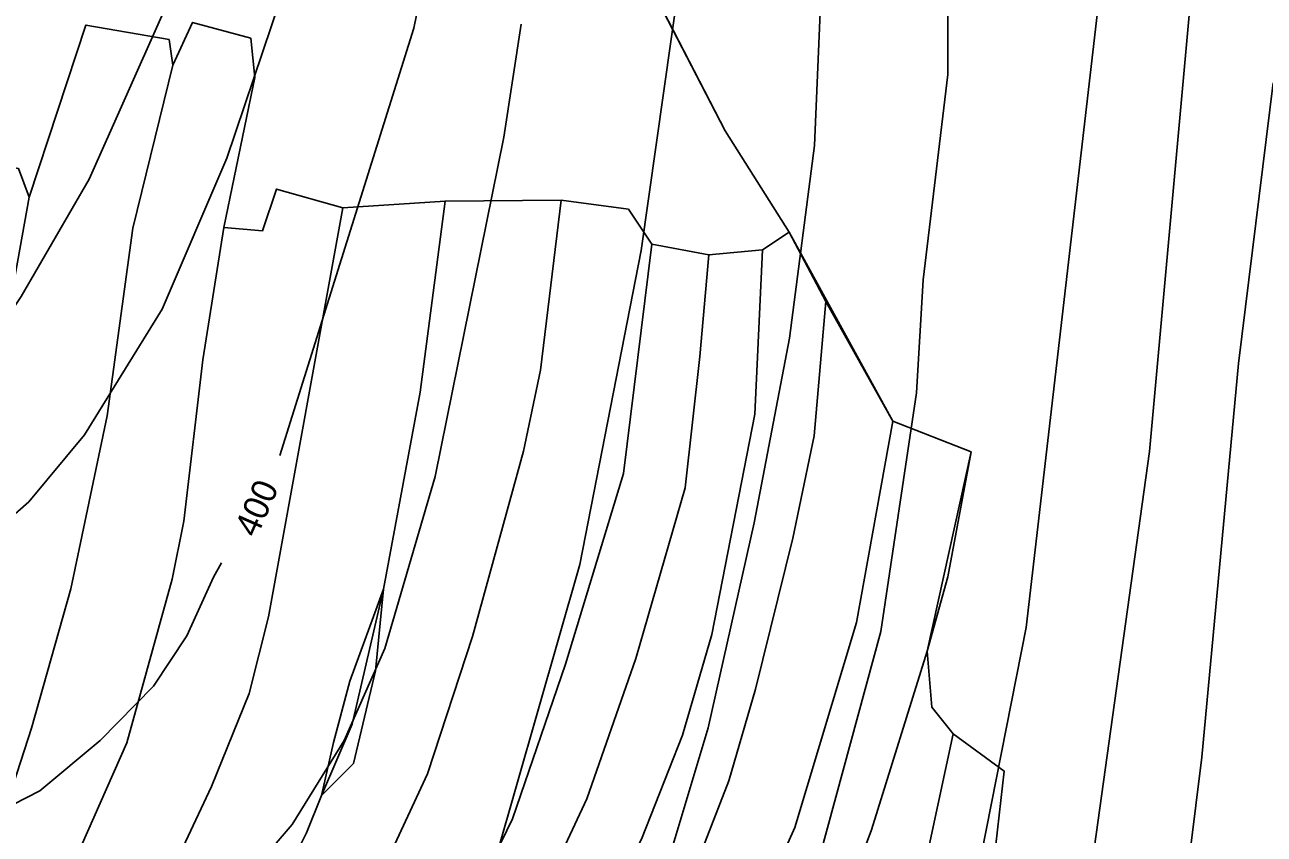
# Model space of a CAD drawing. Extents: x -510989 to -501240, y -1184665 to -1176098.
# Drawn here: x -501918.7 to -501623.1, y -1183267.4 to -1183074.2 of the extents above; entities that cross this region are included whole.
import ezdxf

# ---------------------------------------------------------------- set-up
doc = ezdxf.new("R2010")
doc.units = 0
for name, color, linetype in [('lesni_pozemek', 7, 'Continuous'), ('orna_puda', 7, 'Continuous'), ('popis', 7, 'Continuous'), ('STAV_zaplavove_uzemi', 7, 'Continuous'), ('trvaly_travni_porost', 7, 'Continuous'), ('vrstevnice_01', 7, 'Continuous'), ('vrstevnice_02', 7, 'Continuous'), ('vrstevnice_04', 7, 'Continuous')]:
    doc.layers.add(name, color=color, linetype=linetype)

msp = doc.modelspace()

# ---------------------------------------------------------------- linework, layer by layer
at = {"layer": 'lesni_pozemek'}
msp.add_lwpolyline([(-501783.55, -1183037.66), (-501751.63, -1183099.46), (-501736.36, -1183123.66), (-501742.71, -1183127.87), (-501755.51, -1183129.09), (-501769.14, -1183126.53), (-501774.69, -1183118.15), (-501790.7, -1183116.04), (-501818.4, -1183116.24), (-501842.79, -1183117.88), (-501858.62, -1183113.36), (-501861.95, -1183123.31), (-501871.15, -1183122.57), (-501863.8, -1183086.72), (-501864.77, -1183077.37), (-501878.63, -1183073.61), (-501883.32, -1183083.77), (-501884.24, -1183077.69), (-501904.1, -1183074.23), (-501917.6, -1183115.27), (-501920.15, -1183108.47)], dxfattribs=at)
at = {"layer": 'orna_puda'}
for points in [[(-501904.1, -1183074.23), (-501884.24, -1183077.69), (-501883.32, -1183083.77), (-501892.93, -1183122.67), (-501899.03, -1183167.53), (-501907.67, -1183208.78), (-501917.05, -1183242.02), (-501926.59, -1183271.34), (-501937.55, -1183292.58), (-501958.27, -1183326.06), (-501975.2, -1183320.45), (-501955.04, -1183286.9), (-501945.61, -1183264.95), (-501940.28, -1183250.99), (-501931.27, -1183221.12), (-501924.09, -1183185.46), (-501925.8, -1183185.09), (-501927.7, -1183184.68), (-501926.03, -1183161.85), (-501917.6, -1183115.27)], [(-501864.77, -1183077.37), (-501863.8, -1183086.72), (-501871.15, -1183122.57), (-501876.22, -1183154.15), (-501880.72, -1183192.62), (-501883.48, -1183206.51), (-501894.31, -1183245.56), (-501908.55, -1183277.79), (-501921.04, -1183303.18), (-501926.52, -1183312.48), (-501942.3, -1183332.24), (-501958.27, -1183326.06), (-501937.55, -1183292.58), (-501926.59, -1183271.34), (-501917.05, -1183242.02), (-501907.67, -1183208.78), (-501899.03, -1183167.53), (-501892.93, -1183122.67), (-501883.32, -1183083.77), (-501878.63, -1183073.61)], [(-501790.7, -1183116.04), (-501795.7, -1183156.61), (-501799.74, -1183175.95), (-501811.85, -1183220.19), (-501822.62, -1183252.98), (-501849.76, -1183311.31), (-501868.66, -1183343.98), (-501918.3, -1183419.01), (-501932.79, -1183407.16), (-501929.55, -1183401.1), (-501894.25, -1183346.1), (-501876.03, -1183316.67), (-501861.62, -1183288.7), (-501854.23, -1183272.61), (-501851.47, -1183267.01), (-501847.92, -1183258.15), (-501840.27, -1183250.44), (-501834.99, -1183228.35), (-501833.1, -1183208.87), (-501824.36, -1183161.87), (-501818.4, -1183116.24)], [(-501727.6, -1183140.18), (-501711.62, -1183168.77), (-501720.3, -1183216.84), (-501735.02, -1183265.79), (-501753.16, -1183306.3), (-501779.62, -1183352.75), (-501796.75, -1183385.32), (-501809.68, -1183407.48), (-501827.68, -1183438.15), (-501845.48, -1183470.88), (-501848.32, -1183476.3), (-501865.93, -1183461.89), (-501840.28, -1183410.81), (-501832.45, -1183400.75), (-501813.53, -1183372.42), (-501772.03, -1183302.69), (-501759, -1183275.94), (-501750.72, -1183254.61), (-501744.35, -1183232.74), (-501735.47, -1183196.68), (-501730.42, -1183172.31)], [(-501711.62, -1183168.77), (-501692.95, -1183176.11), (-501698.49, -1183205.93), (-501703.45, -1183223.64), (-501716.73, -1183266.29), (-501727.09, -1183294.03), (-501741.13, -1183321.98), (-501764.22, -1183362.91), (-501773.41, -1183384.54), (-501781.88, -1183401.83), (-501791.82, -1183419.56), (-501809.68, -1183407.48), (-501796.75, -1183385.32), (-501779.62, -1183352.75), (-501753.16, -1183306.3), (-501735.02, -1183265.79), (-501720.3, -1183216.84)], [(-501834.99, -1183228.35), (-501840.27, -1183250.44), (-501847.92, -1183258.15), (-501840.61, -1183241.11), (-501833.1, -1183208.87)]]:
    msp.add_lwpolyline(points, close=True, dxfattribs=at)
at = {"layer": 'popis'}
msp.add_lwpolyline([(-501767.59, -1183068.56), (-501751.63, -1183099.46), (-501736.36, -1183123.66), (-501711.62, -1183168.77), (-501692.95, -1183176.11), (-501703.45, -1183223.64), (-501702.33, -1183237.02), (-501697.22, -1183243.37), (-501685.1, -1183252.28), (-501687.86, -1183276.78), (-501693.69, -1183298.22), (-501660.44, -1183309.36), (-501644.79, -1183312.71), (-501631.61, -1183317.53), (-501621.11, -1183386.62)], dxfattribs=at)
at = {"layer": 'STAV_zaplavove_uzemi'}
msp.add_spline([(-502765.18, -1180820.83), (-502819.12, -1180854.68), (-502855.09, -1180856.79), (-502878.36, -1180851.5), (-502911.15, -1180848.33), (-502954.52, -1180870.54), (-502984.14, -1180869.48), (-503005.29, -1180861.02), (-503048.66, -1180872.66), (-503074.04, -1180895.93), (-503100.49, -1180910.74), (-503124.82, -1180934.01), (-503148.09, -1180961.51), (-503167.13, -1180991.13), (-503214.18, -1181039.04), (-503223.14, -1181058.24), (-503224.42, -1181086.39), (-503233.38, -1181129.91), (-503224.42, -1181152.95), (-503210.34, -1181174.71), (-503189.86, -1181187.51), (-503177.06, -1181216.94), (-503187.3, -1181265.58), (-503182.09, -1181326.92), (-503202.22, -1181367.18), (-503223.9, -1181396.6), (-503227, -1181422.93), (-503244.04, -1181475.59), (-503248.68, -1181509.66), (-503278.16, -1181558.16), (-503308.83, -1181601.52), (-503351.14, -1181645.95), (-503365.95, -1181659.7), (-503395.57, -1181685.09), (-503411.43, -1181722.11), (-503422.01, -1181739.03), (-503437.88, -1181747.49), (-503460.09, -1181743.26), (-503481.25, -1181748.55), (-503492.88, -1181761.25), (-503472.79, -1181803.56), (-503443.17, -1181840.58), (-503413.55, -1181857.5), (-503278.84, -1181941.97), (-503242.23, -1181977.17), (-503180.29, -1182027.85), (-503125.38, -1182098.25), (-503088.78, -1182167.23), (-503075.54, -1182217), (-503114.26, -1182162.8), (-503152.97, -1182091.56), (-503197.89, -1182048.2), (-503210.28, -1182032.71), (-503231.96, -1182021.87), (-503259.83, -1182017.22), (-503266.03, -1182021.87), (-503224.21, -1182048.2), (-503199.43, -1182076.07), (-503157.62, -1182114.79), (-503135.94, -1182159.7), (-503118.9, -1182207.71), (-503111.16, -1182251.07), (-503108.24, -1182409.43), (-503115.92, -1182478.55), (-503128.72, -1182603.98), (-503131.28, -1182696.13), (-503104.4, -1182780.6), (-503071.45, -1182869.91), (-503052.71, -1182886.94), (-502977.76, -1182944.86), (-502838.07, -1183047.07), (-502664.31, -1183174.84), (-502563.8, -1183270.24), (-502485.44, -1183353.71), (-502446.26, -1183432.07), (-502383.48, -1183571.46), (-502315.46, -1183658.04), (-502253.62, -1183724), (-502158.8, -1183808.51), (-502045.43, -1183923.94), (-501930, -1184016.7), (-501793.89, -1184089.91), (-501746.5, -1184127.32), (-501709.09, -1184197.15)], degree=3, dxfattribs=at)
at = {"layer": 'trvaly_travni_porost'}
for points in [[(-501939.04, -1183105.33), (-501920.15, -1183108.47), (-501917.6, -1183115.27), (-501926.03, -1183161.85), (-501927.7, -1183184.68), (-501940.41, -1183231.82), (-501961.97, -1183286.23), (-501970.7, -1183302.31), (-501984.91, -1183323.55), (-502007.13, -1183315.74), (-501986.28, -1183288.64), (-501976.06, -1183263.83), (-501967.18, -1183235.02), (-501963.34, -1183220.66)], [(-501842.79, -1183117.88), (-501860.57, -1183215.5), (-501865.16, -1183233.81), (-501874.15, -1183255.99), (-501890.23, -1183290.34), (-501909.87, -1183326.35), (-501919.02, -1183341.77), (-501934.97, -1183333.67), (-501926.52, -1183312.48), (-501921.04, -1183303.18), (-501908.55, -1183277.79), (-501894.31, -1183245.56), (-501883.48, -1183206.51), (-501880.72, -1183192.62), (-501876.22, -1183154.15), (-501871.15, -1183122.57), (-501861.95, -1183123.31), (-501858.62, -1183113.36)], [(-501842.79, -1183117.88), (-501818.4, -1183116.24), (-501824.36, -1183161.87), (-501833.1, -1183208.87), (-501841.17, -1183230.81), (-501845.07, -1183245.44), (-501847.92, -1183258.15), (-501851.47, -1183267.01), (-501854.23, -1183272.61), (-501884.67, -1183321.22), (-501897.16, -1183343.35), (-501916.34, -1183369.09), (-501931.26, -1183387.1), (-501940.17, -1183400.08), (-501949.48, -1183390.86), (-501939.58, -1183374.46), (-501919.02, -1183341.77), (-501909.87, -1183326.35), (-501890.23, -1183290.34), (-501874.15, -1183255.99), (-501865.16, -1183233.81), (-501860.57, -1183215.5)], [(-501774.69, -1183118.15), (-501769.14, -1183126.53), (-501775.88, -1183181.28), (-501789.73, -1183226.8), (-501802.34, -1183263.68), (-501818.79, -1183297.59), (-501832.21, -1183322.52), (-501860.49, -1183367.59), (-501884.73, -1183396.77), (-501904.3, -1183430.47), (-501918.3, -1183419.01), (-501868.66, -1183343.98), (-501849.76, -1183311.31), (-501822.62, -1183252.98), (-501811.85, -1183220.19), (-501799.74, -1183175.95), (-501795.7, -1183156.61), (-501790.7, -1183116.04)], [(-501736.36, -1183123.66), (-501727.6, -1183140.18), (-501730.42, -1183172.31), (-501735.47, -1183196.68), (-501744.35, -1183232.74), (-501750.72, -1183254.61), (-501759, -1183275.94), (-501772.03, -1183302.69), (-501813.53, -1183372.42), (-501832.45, -1183400.75), (-501841.94, -1183394.13), (-501822.97, -1183363.61), (-501801.51, -1183326.54), (-501771.61, -1183268.57), (-501761.79, -1183243.72), (-501754.79, -1183219.69), (-501744.54, -1183167.09), (-501742.71, -1183127.87)], [(-501755.51, -1183129.09), (-501757.63, -1183153.37), (-501761.19, -1183184.69), (-501772.96, -1183225.38), (-501784.58, -1183258.94), (-501801.28, -1183294.62), (-501828.74, -1183348.28), (-501852.05, -1183386.85), (-501868.84, -1183412.66), (-501889.23, -1183442.81), (-501898.02, -1183435.61), (-501893.52, -1183428.14), (-501894.52, -1183427.34), (-501874.16, -1183390.23), (-501866.72, -1183391.22), (-501842.37, -1183347.61), (-501832.21, -1183322.52), (-501818.79, -1183297.59), (-501802.34, -1183263.68), (-501789.73, -1183226.8), (-501775.88, -1183181.28), (-501769.14, -1183126.53)], [(-501742.71, -1183127.87), (-501744.54, -1183167.09), (-501754.79, -1183219.69), (-501761.79, -1183243.72), (-501771.61, -1183268.57), (-501801.51, -1183326.54), (-501822.97, -1183363.61), (-501841.94, -1183394.13), (-501852.05, -1183386.85), (-501828.74, -1183348.28), (-501801.28, -1183294.62), (-501784.58, -1183258.94), (-501772.96, -1183225.38), (-501761.19, -1183184.69), (-501757.63, -1183153.37), (-501755.51, -1183129.09)], [(-501833.1, -1183208.87), (-501840.61, -1183241.11), (-501847.92, -1183258.15), (-501845.07, -1183245.44), (-501841.17, -1183230.81)], [(-501697.22, -1183243.37), (-501685.1, -1183252.28), (-501687.86, -1183276.78), (-501693.69, -1183298.22), (-501705.88, -1183332.07), (-501744.33, -1183414.33), (-501764.06, -1183450.58), (-501785.54, -1183494.15), (-501834.1, -1183592.16), (-501845.04, -1183613.22), (-501859.14, -1183601.84), (-501837.85, -1183558.19), (-501821.13, -1183522.17), (-501798.89, -1183475.85), (-501779.6, -1183441.26), (-501759.07, -1183400.58), (-501742.72, -1183365.69), (-501727.22, -1183334.28), (-501712.03, -1183298.88), (-501704.56, -1183277.45)]]:
    msp.add_lwpolyline(points, close=True, dxfattribs=at)
msp.add_lwpolyline([(-501727.09, -1183294.03), (-501716.73, -1183266.29), (-501703.45, -1183223.64), (-501702.33, -1183237.02), (-501697.22, -1183243.37), (-501704.56, -1183277.45)], dxfattribs=at)
at = {"layer": 'vrstevnice_01'}
for points in [[(-501807.41, -1182985), (-501825.91, -1183075), (-501857.86, -1183176.97)], [(-501751.91, -1182989), (-501771.69, -1183128), (-501786.31, -1183203), (-501806.31, -1183273), (-501815.09, -1183296), (-501827.19, -1183319), (-501843.91, -1183344), (-501860.09, -1183361), (-501876.09, -1183372), (-501884.91, -1183375), (-501898, -1183376), (-501912.31, -1183374), (-501931.5, -1183366)], [(-502239.41, -1183029), (-502213.69, -1183081), (-502191.41, -1183121), (-502179.59, -1183139), (-502164.81, -1183158), (-502149.5, -1183173), (-502106, -1183196), (-502075.41, -1183209), (-502057.5, -1183213), (-502030.91, -1183212), (-502015.41, -1183210), (-501986.09, -1183200), (-501974.31, -1183195), (-501957.09, -1183183), (-501943.19, -1183171), (-501932.81, -1183159), (-501919.5, -1183139), (-501903.31, -1183111), (-501886, -1183072)], [(-501871.74, -1183202.6), (-501873.69, -1183206), (-501880, -1183220), (-501888, -1183232), (-501900.69, -1183245), (-501915.09, -1183257), (-501930.81, -1183265), (-501962.69, -1183273), (-501984, -1183275), (-502006.69, -1183274), (-502060.59, -1183261), (-502088, -1183253), (-502155.81, -1183214), (-502175.81, -1183200), (-502196.19, -1183178), (-502212.69, -1183152), (-502261.41, -1183051)], [(-501971.81, -1183436), (-501916.69, -1183467), (-501845.41, -1183506), (-501826.19, -1183514), (-501810.31, -1183518), (-501780.69, -1183516), (-501765.09, -1183512), (-501752.59, -1183506), (-501739.5, -1183497), (-501721.31, -1183481), (-501711.41, -1183467), (-501702, -1183451), (-501698.19, -1183442), (-501687.81, -1183409), (-501664.91, -1183280), (-501650.41, -1183176), (-501640.19, -1183063)], [(-501698.5, -1183071), (-501698.5, -1183086), (-501704.41, -1183135), (-501706, -1183162), (-501714.5, -1183219), (-501745.19, -1183332), (-501759.5, -1183367), (-501765.69, -1183380), (-501783.09, -1183405), (-501792.81, -1183413), (-501808, -1183423), (-501822.19, -1183428), (-501853.59, -1183435), (-501866.69, -1183435), (-501882.41, -1183433), (-501906.09, -1183426), (-501926.19, -1183416)]]:
    msp.add_lwpolyline(points, dxfattribs=at)
at = {"layer": 'vrstevnice_02'}
for points in [[(-501974.81, -1183410), (-501909.19, -1183442), (-501877.5, -1183454), (-501855.59, -1183461), (-501811.5, -1183471), (-501800.19, -1183471), (-501775.5, -1183461), (-501761.31, -1183451), (-501752, -1183442), (-501744.59, -1183430), (-501732.59, -1183407), (-501722.31, -1183379), (-501703.69, -1183320), (-501690.5, -1183272), (-501679.81, -1183218), (-501660.31, -1183049)], [(-501736.31, -1183149), (-501730.31, -1183103), (-501728.41, -1183058)], [(-501857.69, -1183068), (-501870.5, -1183106), (-501885.91, -1183142), (-501904.41, -1183172), (-501917.69, -1183188), (-501950.69, -1183217), (-501960.19, -1183224), (-501972.19, -1183230), (-501989.31, -1183235), (-502018.59, -1183239), (-502058.41, -1183237), (-502070, -1183234), (-502091.69, -1183226), (-502143.5, -1183201), (-502162.91, -1183188), (-502180.69, -1183171), (-502197.69, -1183145), (-502236.91, -1183063)], [(-501930.91, -1183312), (-501914.31, -1183311), (-501906.19, -1183308), (-501891.31, -1183302), (-501874.59, -1183288), (-501854.91, -1183265), (-501842.5, -1183245), (-501832.81, -1183223), (-501820.81, -1183182), (-501804.41, -1183101), (-501800.31, -1183074)], [(-501620.91, -1183088), (-501629.19, -1183155), (-501637.91, -1183249), (-501645, -1183306), (-501648.69, -1183324), (-501659.91, -1183403), (-501670.91, -1183463), (-501676.5, -1183484), (-501684.81, -1183504), (-501697, -1183527), (-501710.91, -1183544), (-501729.09, -1183556), (-501738.5, -1183559), (-501758.09, -1183562), (-501781.31, -1183561), (-501799.31, -1183557), (-501815.81, -1183552), (-501836.19, -1183541), (-501925.09, -1183487)], [(-501919.91, -1183393), (-501902, -1183400), (-501881.91, -1183405), (-501863.31, -1183405), (-501844.69, -1183400), (-501831.59, -1183394), (-501813, -1183379), (-501804.31, -1183368), (-501788.09, -1183340), (-501774.31, -1183304), (-501755.69, -1183242), (-501744.69, -1183193), (-501736.31, -1183149)]]:
    msp.add_lwpolyline(points, dxfattribs=at)

# ---------------------------------------------------------------- texts
at = {"layer": 'vrstevnice_04'}
msp.add_text('400', height=6, rotation=66.1942, dxfattribs=at).set_placement((-501863.38, -1183196.81))

doc.saveas('drawing.dxf')
